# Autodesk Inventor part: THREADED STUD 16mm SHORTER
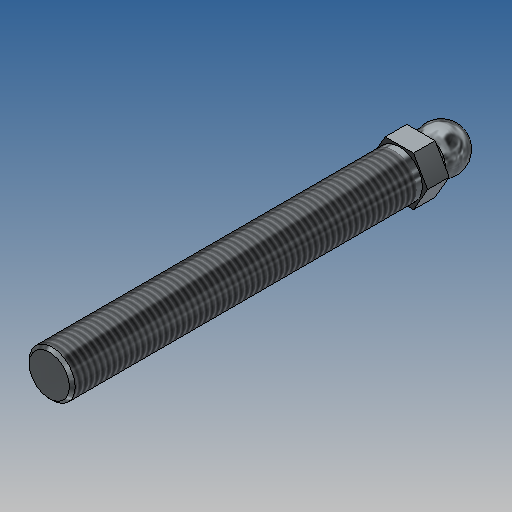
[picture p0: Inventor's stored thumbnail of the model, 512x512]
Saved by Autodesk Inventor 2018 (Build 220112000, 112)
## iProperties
Created: 2007-03
Part Number: THREADED STUD 16mm SHORTER
Document SubType Name: Modeling
Designer: Andy Moles
Material: Steel
Mass: 220.963 g
Surface Area: 75.6538 cm^2
Volume: 28.1482 cm^3
Density: 7.85 g/cm^3
Appearance: Zinc
Author: Andy Moles
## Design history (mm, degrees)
sketch "Sketch1"
  geometry: L1 (0, -7.5)-(0, 7.5); A1 r 7.5 centre (0, 0) between (0, -7.5) and (0, 7.5); 1 further point
  constraints: 2 end point, 2 point on circle, 1 centre point, 1 coincident, 1 midpoint, 1 vertical
  dimensions: "d5" = 15 distance of L1.start L1.end
revolve "Revolution1" sketch "Sketch1" stored, may be unused: angle "d1" = 90 deg
sketch "Sketch2"
  geometry: C1 r 6 at (0, 0); 1 further point
  constraints: 1 centre point, 1 coincident
  dimensions: "d2" = 12 diameter of C1
extrude "Extrusion1" join sketch "Sketch2" distance "d3" = 7; taper "d4" = 0 deg
sketch "Sketch3"
  geometry: L1 (-4.907, 8.5)-(4.907, 8.5); L2 (4.907, 8.5)-(9.815, 0); L3 (9.815, 0)-(4.907, -8.5); L4 (4.907, -8.5)-(-4.907, -8.5); L5 (-4.907, -8.5)-(-9.815, 0); L6 (-9.815, 0)-(-4.907, 8.5); C1 r 6 at (0, 0) reference; 1 further point
  constraints: 12 end point, 5 equal length, 1 horizontal, 1 horizontal alignment, 1 midpoint, 1 parallel, 1 vertical alignment
  dimensions: "d6" = 120 deg angle of L6 L5; "d7" = 120 deg angle of L1 L6; "d8" = 17 distance between parallel lines of L4 L1
extrude "Extrusion2" join sketch "Sketch3" distance "d9" = 7.5; taper "d10" = 0 deg
sketch "Sketch4"
  geometry: C1 r 8 at (0, 0); 1 further point
  constraints: 1 centre point, 1 coincident
  dimensions: "d11" = 16 diameter of C1
extrude "Extrusion3" join sketch "Sketch4" distance "d12" = 121.5; taper "d13" = 0 deg
thread "Thread1" dims "d14" = 148, "d15" = 2
chamfer "Chamfer1" distance "d16" = 1; stored, may be unused: second distance "d17" = 2, angle "d18" = 45 deg
body "Solid1"
